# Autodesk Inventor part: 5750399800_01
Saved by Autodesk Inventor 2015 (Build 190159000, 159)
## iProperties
Created: 2020-07
Part Number: 5750399800_01
Checked By: TraceParts S.A.
Material: Generic
Catalog Web Link: www.traceparts.com
Document SubType Name: Modeling
Designer: TraceParts
Density: 1 g/cm^3
Appearance: Default
Company: TraceParts S.A.
Author: TraceParts
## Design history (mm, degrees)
feature "5750399800_01.ipt"
body "Solid1"
